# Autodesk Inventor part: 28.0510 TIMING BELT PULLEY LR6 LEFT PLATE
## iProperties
Created: 2007-06
Part Number: 28.0510 TIMING BELT PULLEY LR6 LEFT PLATE
Document SubType Name: Modeling
Designer: Andy Moles
Material: Aluminum-6061
Mass: 286.145 g
Surface Area: 351.47 cm^2
Volume: 105.589 cm^3
Density: 2.71 g/cm^3
Author: Andy Moles
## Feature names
1. Extrusion1
2. Hole1
3. Hole2
4. Extrusion2
5. Extrusion3
6. Extrusion4
7. Extrusion5
8. Extrusion6
9. Fillet1
10. Extrusion7
11. Extrusion8
12. Extrusion9
13. Extrusion10
14. Hole3
15. Extrusion11
16. Extrusion12
17. Extrusion13
18. Hole4
19. Extrusion14
20. Extrusion15
21. Extrusion16
